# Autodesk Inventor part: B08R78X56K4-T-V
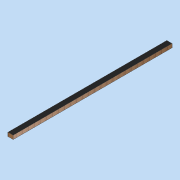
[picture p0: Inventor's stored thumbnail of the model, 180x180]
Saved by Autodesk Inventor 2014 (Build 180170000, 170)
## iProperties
Created: 2011-08
Part Number: B08R78X56K4-T-V
Document SubType Name: Modeling
Designer: david.appleford
Density: 0.482584 g/cm^3
Description: Roof Edge Beam 2w - 4 Locks
Mass: 5000 g
Surface Area: 6444.32 cm^2
Volume: 10360.9 cm^3
Cost Center: £27.00
Material: 000 Redwood
Appearance: Wood (Oak)
Justset: False
Title: Roof Edge Beam 2w - 4 Locks
Author: david.appleford
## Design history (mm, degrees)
sketch "Sketch1"
  geometry: L1 (39, -34)-(-39, -34); L2 (-39, -34)-(-39, 2338); L3 (-39, 2338)-(39, 2338); L4 (39, 2338)-(39, -34); 1 further point
  constraints: 8 end point, 2 parallel, 1 horizontal, 1 perpendicular, 1 other
  dimensions: "d2" = 78 distance between parallel lines of L2 L4; "d3" = 34 distance from line of point (0, 0) L1; "d4" = 39 distance from line of point (0, 0) L2 (= 0.5 x d2); "d5" = 2372 distance of L3.end L1.start
extrude "Extrusion1" new body sketch "Sketch1" distance "d0" = 56; taper "d1" = 0 deg
body "Solid1"
